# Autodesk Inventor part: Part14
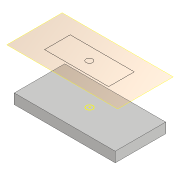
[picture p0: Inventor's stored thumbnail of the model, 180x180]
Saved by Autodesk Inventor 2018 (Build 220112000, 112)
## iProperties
Created: 2015-05
Part Number: Part14
Material: Generic
Document SubType Name: Modeling
Designer: Sandeep
Density: 1 g/cm^3
Appearance: Default
Author: Sandeep
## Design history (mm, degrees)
sketch "Sketch1"
  geometry: L1 (-100, 50)-(100, 50); L2 (100, 50)-(100, -50); L3 (100, -50)-(-100, -50); L4 (-100, -50)-(-100, 50); 1 further point
  constraints: 8 end point, 2 parallel, 1 horizontal, 1 perpendicular
  dimensions: "d0" = 100 distance from line of point (0, 0) L2; "d1" = 200 distance of L1.start L1.end; "d2" = 50 distance from line of point (0, 0) L1; "d3" = 100 distance of L1.end L2.end
extrude "Extrusion1" new body sketch "Sketch1" distance "d4" = 20; taper "d5" = 0 deg
workplane "Work Plane1"
sketch "Sketch2"
  geometry: C1 r 6.35 at (-0.807, -0.346) reference; 1 further point
body "Solid1"
